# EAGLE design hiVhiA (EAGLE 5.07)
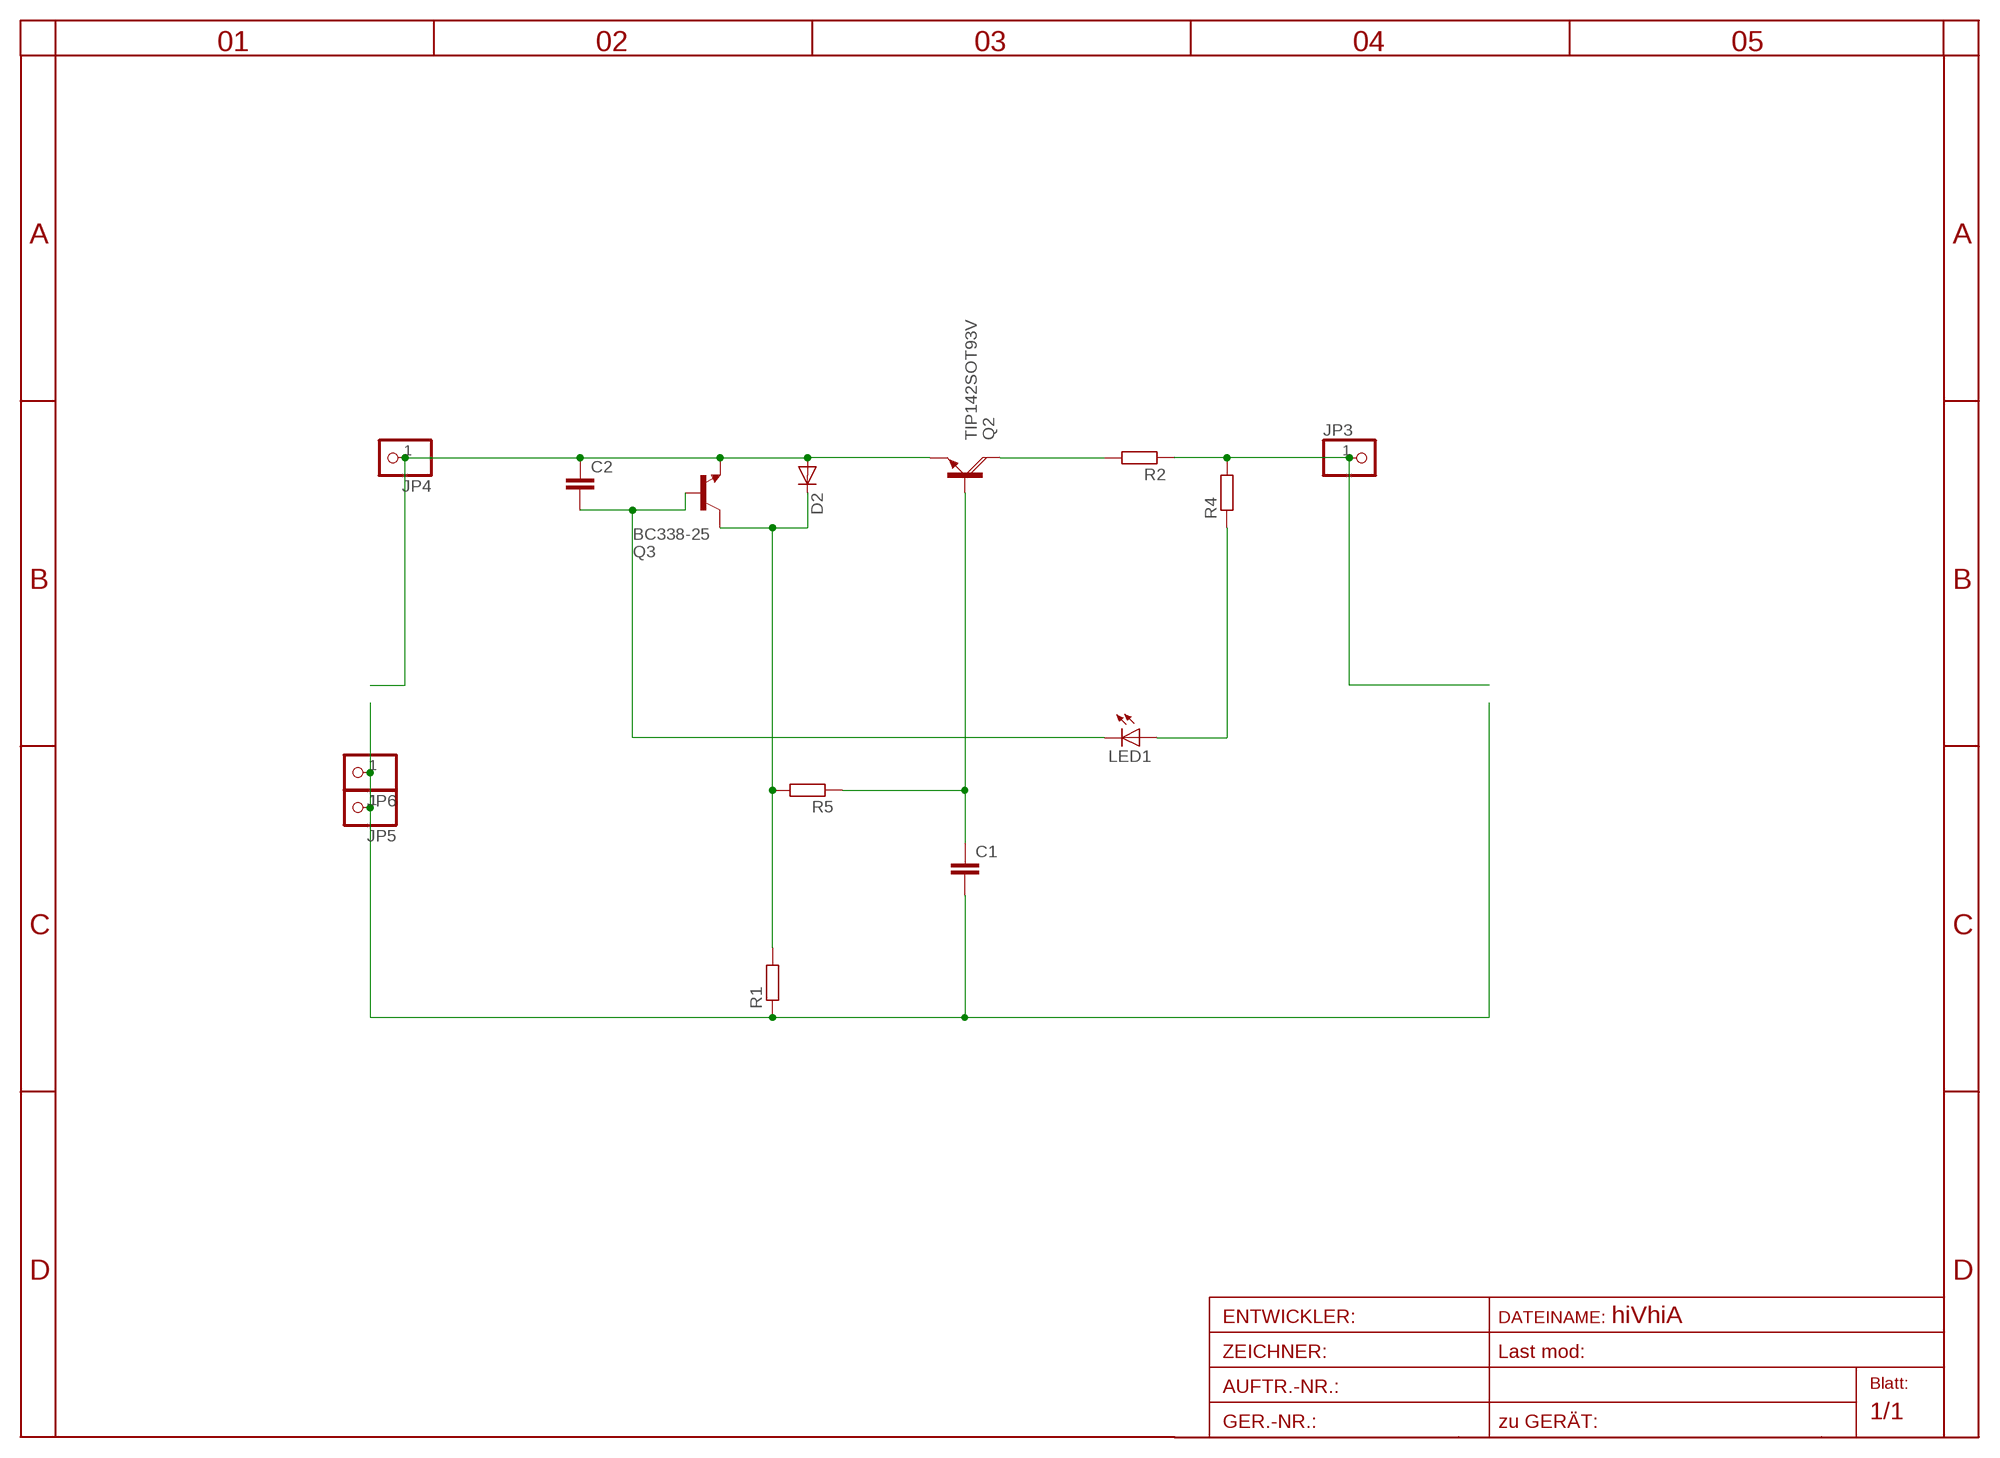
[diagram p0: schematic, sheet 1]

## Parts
C1  C-EU025-040X050  [C025-040X050]
C2  C-EU025-024X044  [C025-024X044]
D2  DIODE-D-5  [D-5]
JP3  PINHD-1X12MM3  [1X2MM3]
JP4  PINHD-1X12MM3  [1X2MM3]
JP5  PINHD-1X12MM3  [1X2MM3]
JP6  PINHD-1X12MM3  [1X2MM3]
LED1  LED3MM  [LED3MM]
Q2  TIP142SOT93V  [SOT93V]
Q3  BC338-25  [TO92-EBC]
R1  R-EU_0204/5  [0204/5]
R2  R-EU_0204/5  [0204/5]
R4  R-EU_0207/22  [0207/22]
R5  R-EU_0204/5  [0204/5]

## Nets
N$1: C1.2 JP5.1 JP6.1 R1.1
N$2: C2.1 D2.A JP4.1 Q2.E Q3.E
N$3: Q2.C R2.2
N$4: D2.C Q3.C R1.2 R5.2
N$7: C1.1 Q2.B R5.1
N$8: JP3.1 R2.1 R4.2
N$11: LED1.A R4.1
N$12: C2.2 LED1.K(C) Q3.B

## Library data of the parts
C1 C2 = rcl-2:C-EU: CAPACITOR, European symbol
D2 = diode-1:DIODE-: DIODE
JP3-JP6 = pinhead:PINHD-1X1: PIN HEADER
LED1 = led:LED: LED
Q2 = transistor-power:TIP142: NPN DARLINGTON TRANSISTOR
Q3 = transistor-npn:BC338*: NPN Transistor
R1 R2 R4 R5 = rcl-2:R-EU_: RESISTOR, European symbol

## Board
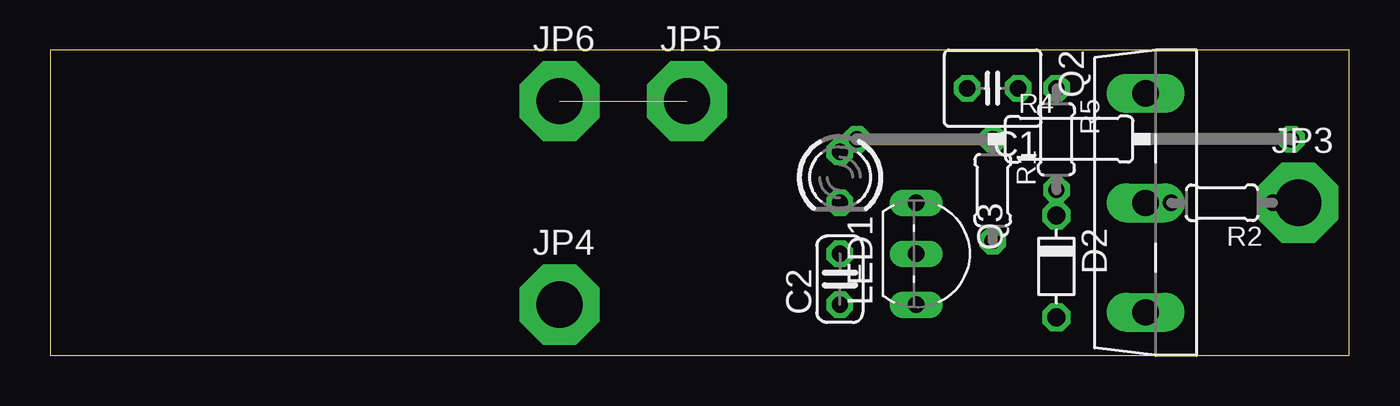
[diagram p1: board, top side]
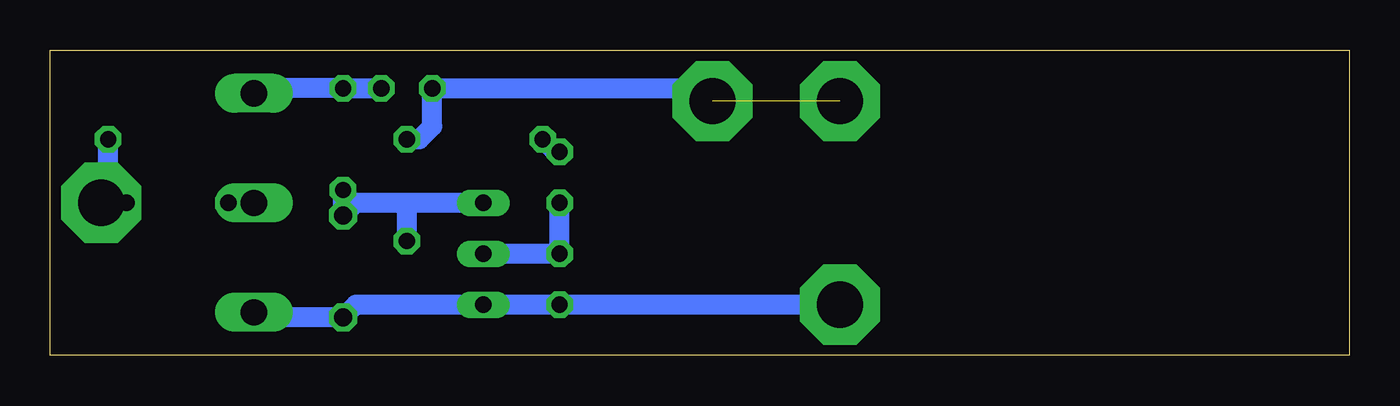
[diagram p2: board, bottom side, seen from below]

Size 64.77 x 15.24 mm. Coordinates in mm from the lower left corner, seen from the top.
Outline: 0,0 64.77,0 64.77,15.24 0,15.24 0,0
Copper layers (1*16): Top 0.035mm / dielectric 1.5mm / Bottom 0.035mm
Design rules "default": minimum track width 10mil, minimum drill 24mil, track to track 8mil, track to pad 8mil, pad to pad 8mil, via to via 8mil, smd to smd 8mil, copper to edge 40mil, drill to drill 8mil, minimum pad ring 10mil, minimum via ring 8mil, stop-mask expansion 4mil, vias tented up to drill 0mil, thermal gap 10mil

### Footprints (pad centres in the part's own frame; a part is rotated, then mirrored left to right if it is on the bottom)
C025-040X050 = drill 0.813 octagon: 1 -1.27,0; 2 1.27,0
C025-024X044 = drill 0.813 octagon: 1 -1.27,0; 2 1.27,0
D-5 = drill 0.9 octagon: A 2.54,0; C -2.54,0
1X2MM3 = drill 2.3 pad 4 octagon: 1 0,0
LED3MM = drill 0.813 octagon: A -1.27,0; K 1.27,0
SOT93V = drill 1.3 pad 1.676 long: B -5.461,-2.54; C 0,-2.54; E 5.461,-2.54
TO92-EBC = drill 0.813 long: B 0,-1.27; C -2.54,-1.27; E 2.54,-1.27
0204/5 = drill 0.813 octagon: 1 -2.54,0; 2 2.54,0
0207/22 = drill 0.813 octagon: 1 -10.58,0; 2 11.08,0

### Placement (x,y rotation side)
C1  46.99,13.34 180 top
C2  39.37,3.81 90 top
D2  50.16,4.45 270 top
JP3  62.23,7.62 0 top
JP4  25.4,2.54 0 top
JP5  31.75,12.7 0 top
JP6  25.4,12.7 0 top
LED1  39.37,8.89 270 top
Q2  57.15,7.62 270 top
Q3  44.45,5.08 270 top
R1  46.99,8.26 270 top
R2  58.42,7.62 180 top
R4  50.8,10.79 0 top
R5  50.16,10.79 270 top

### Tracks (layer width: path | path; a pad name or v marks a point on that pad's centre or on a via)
N$1  (1 unrouted)
  Bottom 1: R1.1 46.35,10.79 45.72,11.43 C1.2 32.38,13.34 JP5.1
N$2
  Bottom 1: JP4.1 C2.1 Q3.E 49.53,2.54 D2.A 54.36,1.91 Q2.E
N$3
  Bottom 1: Q2.C R2.2
N$4
  Bottom 1: Q3.C 46.99,7.62 | 46.99,7.62 49.53,7.62 D2.C R5.2 | 46.99,7.62 R1.2
N$7
  Bottom 1: C1.1 R5.1 54.36,13.34 Q2.B
N$8
  Bottom 1: R2.1 JP3.1 61.88,7.97 R4.2
N$11
  Bottom 1: LED1.A 39.59,10.16 R4.1
N$12
  Bottom 1: Q3.B C2.2 LED1.K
